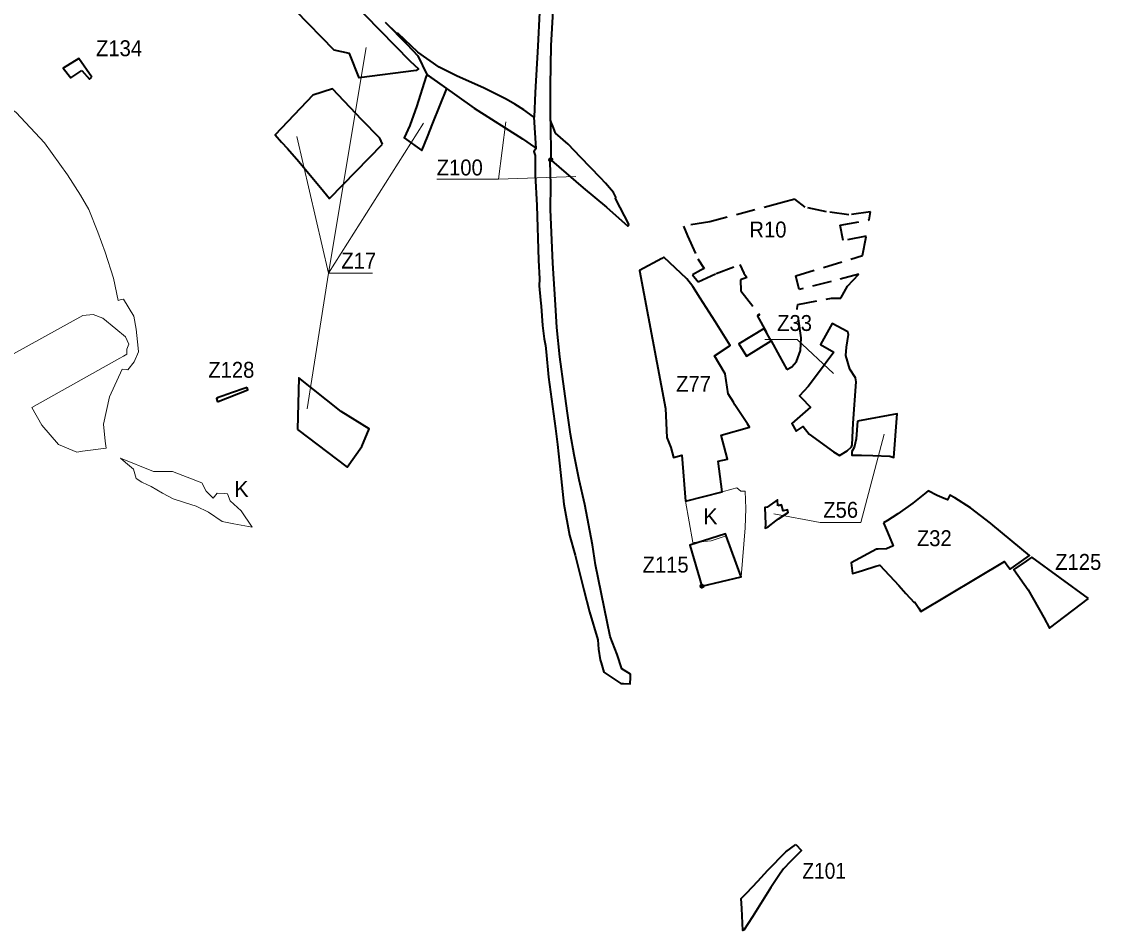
# Model space of a CAD drawing. Extents: x -650276 to -642489, y -1074311 to -1066658.
# Drawn here: x -646145 to -644519, y -1073665 to -1072295 of the extents above; entities that cross this region are included whole.
import ezdxf

# ---------------------------------------------------------------- set-up
doc = ezdxf.new("R2010")
doc.units = 0
doc.header["$LTSCALE"] = 9.6
doc.header["$PDMODE"] = 32
doc.header["$PDSIZE"] = 4.8
doc.linetypes.add('MEDIUM_DASHED', pattern=[4.5, 3, -1.5])
for name, color, linetype, lineweight in [('2', 7, 'Continuous', 40), ('3', 7, 'Continuous', 40), ('4', 7, 'Continuous', 40), ('42', 7, 'Continuous', 25), ('44', 7, 'Continuous', 40), ('45', 7, 'Continuous', 40), ('46', 7, 'Continuous', 13), ('47', 7, 'Continuous', 13), ('48', 7, 'Continuous', 35), ('59', 7, 'Continuous', 13), ('61', 7, 'MEDIUM_DASHED', 40), ('62', 7, 'Continuous', 35)]:
    doc.layers.add(name, color=color, linetype=linetype, lineweight=lineweight)

msp = doc.modelspace()

# ---------------------------------------------------------------- linework, layer by layer
at = {"layer": '2'}
for points in [[(-645834.208, -1072856.314), (-645837.027, -1072857.313), (-645839.908, -1072858.343), (-645842.74, -1072859.344), (-645845.619, -1072860.364), (-645848.628, -1072861.433), (-645851.48, -1072862.586), (-645850.187, -1072866.251), (-645850.17, -1072866.3), (-645849.705, -1072867.618), (-645849.703, -1072867.622)], [(-645849.703, -1072867.622), (-645848.52, -1072867.16), (-645803.84, -1072849.72), (-645805.159, -1072845.994)], [(-645805.159, -1072845.994), (-645808.177, -1072847.063), (-645811.148, -1072848.124), (-645813.978, -1072849.124), (-645816.948, -1072850.184), (-645819.779, -1072851.184), (-645822.726, -1072852.233), (-645825.527, -1072853.233), (-645828.409, -1072854.254), (-645834.208, -1072856.314)], [(-644536.62, -1073164.33), (-644622.03, -1073101.88), (-644630.58, -1073107.78), (-644648.95, -1073120.47), (-644627.53, -1073151.26)], [(-644627.53, -1073151.26), (-644604.13, -1073193), (-644595.18, -1073208.98), (-644536.62, -1073164.33)]]:
    msp.add_lwpolyline(points, dxfattribs=at)
at = {"layer": '3'}
for points in [[(-645503.98, -1072395.64), (-645532.75, -1072375.41), (-645535.05, -1072376.72), (-645549.6, -1072423.39), (-645551.54, -1072428.66), (-645559.92, -1072451.41), (-645568.38, -1072469.68), (-645541.56, -1072488.74), (-645541.09, -1072487.98), (-645533.15, -1072468.21), (-645524.87, -1072447.61)], [(-645600.945, -1072479.473), (-645605.17, -1072470.52), (-645632.1, -1072442.93), (-645632.1, -1072442.93), (-645676.53, -1072396.16), (-645706.039, -1072405.769), (-645763.06, -1072465.26), (-645753.128, -1072476.383), (-645744.38, -1072486.18), (-645726.95, -1072505.7), (-645709.92, -1072526.3), (-645694.51, -1072544.93), (-645680.87, -1072561.42)]]:
    msp.add_lwpolyline(points, close=True, dxfattribs=at)
at = {"layer": '4'}
for points in [[(-646039.16, -1072378.43), (-646058.64, -1072350.29), (-646082.55, -1072364.84), (-646071, -1072379.27), (-646054.43, -1072368.34)], [(-646054.43, -1072368.34), (-646042.65, -1072381.23), (-646039.16, -1072378.43)]]:
    msp.add_lwpolyline(points, dxfattribs=at)
at = {"layer": '42'}
msp.add_lwpolyline([(-644845.72, -1073050.14), (-644839.57, -1073064.5), (-644830.81, -1073084.98), (-644840.89, -1073089.3), (-644853.8, -1073089.99), (-644856.4, -1073090.13), (-644894.15, -1073110.3), (-644892.14, -1073126.36), (-644877.32, -1073121.83), (-644856.97, -1073115.6), (-644851, -1073113.77), (-644822.62, -1073144.71), (-644811.96, -1073156.75), (-644799.26, -1073170.13), (-644798.38, -1073169.56), (-644792.59, -1073178.73), (-644789.31, -1073183.93), (-644663.17, -1073108.27), (-644656.56, -1073117.4), (-644654.61, -1073120.1), (-644649.7, -1073116.65), (-644625.26, -1073099.51), (-644680.69, -1073053.67), (-644684.09, -1073050.8), (-644714.42, -1073027.62), (-644714.42, -1073027.62), (-644737.88, -1073012.62), (-644745.73, -1073008.64), (-644748.95, -1073015.64), (-644757.73, -1073012.05), (-644764.69, -1073008.87), (-644778.38, -1073001.84), (-644781.52, -1073004.39), (-644793.743, -1073014.293), (-644801.54, -1073020.61), (-644824.08, -1073036.56), (-644832.7, -1073042.34), (-644839.47, -1073046.89)], close=True, dxfattribs=at)
at = {"layer": '44'}
for points in [[(-645347.551, -1072443.527), (-645347.677, -1072391.355), (-645346.62, -1072330.914), (-645343.458, -1072278.998), (-645339.908, -1072235.158), (-645335.367, -1072185.207), (-645325.498, -1072102.789), (-645309.01, -1071998.147), (-645285.617, -1071875.733), (-645244.798, -1071696.585), (-645235.793, -1071663.703), (-645230.436, -1071634.261), (-645227.905, -1071625.277), (-645222.48, -1071606.08)], [(-645313.153, -1071883.081), (-645326.343, -1071952.807), (-645334.118, -1072001.954), (-645339.455, -1072031.565), (-645344.819, -1072081.225), (-645351.358, -1072130.815), (-645361.317, -1072232.824), (-645364.435, -1072280.268), (-645366.951, -1072331.609), (-645370.624, -1072401.447), (-645372.228, -1072438.764)], [(-645369.364, -1072485.931), (-645372.228, -1072438.764), (-645373.099, -1072438.135), (-645387.894, -1072427.453), (-645401.441, -1072419.033), (-645414.631, -1072411.611), (-645448.831, -1072394.325), (-645488.64, -1072376.782), (-645515.437, -1072363.447), (-645547.593, -1072340.827), (-645577.33, -1072312.704), (-645579.217, -1072312.425), (-645596.405, -1072296.114)], [(-645596.405, -1072296.114), (-645564.4, -1072328.61), (-645547.72, -1072346.19), (-645534.301, -1072374.332), (-645462.646, -1072425.015)], [(-645462.646, -1072425.015), (-645389.731, -1072471.612), (-645372.013, -1072484.069), (-645369.364, -1072485.931)], [(-645339.904, -1072462.677), (-645342.953, -1072455.042), (-645347.551, -1072443.527), (-645347.292, -1072502.877)], [(-645228.96, -1072600.865), (-645249.9, -1072561.25), (-645248.967, -1072559.511), (-645252.768, -1072552.178), (-645265.009, -1072538.358), (-645272.276, -1072530.154), (-645302.303, -1072499.014), (-645320.805, -1072479.495), (-645339.904, -1072462.677)], [(-645369.364, -1072485.931), (-645372.72, -1072490.314), (-645370.928, -1072496.619), (-645370.755, -1072525.734), (-645368.173, -1072571.881), (-645366.022, -1072654.462), (-645364.524, -1072682.575), (-645364.786, -1072692.977), (-645362.708, -1072714.781)], [(-645338.023, -1072755.969), (-645339.96, -1072721.587), (-645344.152, -1072658.857), (-645347.795, -1072577.893), (-645347.214, -1072540.97), (-645348.253, -1072505.583), (-645347.292, -1072502.877)], [(-645347.292, -1072502.877), (-645346.093, -1072503.921), (-645298.498, -1072545.352)], [(-645298.498, -1072545.352), (-645263.217, -1072574.314), (-645230.845, -1072602.888), (-645228.96, -1072600.865)], [(-645362.708, -1072714.781), (-645361.874, -1072723.527), (-645359.76, -1072752.865), (-645357.272, -1072772.771), (-645355.121, -1072782.993)], [(-645317.65, -1072916.642), (-645322.284, -1072885.085), (-645327.091, -1072848.387), (-645333.718, -1072799.987), (-645338.023, -1072755.969)], [(-645355.121, -1072782.993), (-645354.019, -1072792.454), (-645350.822, -1072830.388), (-645340.345, -1072908.029), (-645337.34, -1072932.073), (-645332.517, -1072974.538), (-645327.554, -1073022.214), (-645319.052, -1073068.6), (-645310.558, -1073098.946), (-645297.395, -1073151.294), (-645288.647, -1073184.518), (-645276.125, -1073226.571), (-645275.269, -1073240.71), (-645272.747, -1073256.762), (-645271.518, -1073261.16)], [(-645304.24, -1072985.372), (-645311.772, -1072947.945), (-645317.65, -1072916.642)], [(-645257.842, -1073221.36), (-645262.388, -1073199.409), (-645279.878, -1073113.356), (-645284.269, -1073083.286), (-645295.788, -1073022.556), (-645304.24, -1072985.372)], [(-645237.524, -1073292.361), (-645227.744, -1073292.735), (-645227.199, -1073283.366), (-645226.847, -1073278.345), (-645239.9, -1073270.025), (-645247.051, -1073248.736), (-645257.842, -1073221.36)], [(-645271.518, -1073261.16), (-645267.525, -1073275.443), (-645241.72, -1073292.2), (-645237.524, -1073292.361)]]:
    msp.add_lwpolyline(points, dxfattribs=at)
at = {"layer": '44', "lineweight": 13}
msp.add_lwpolyline([(-645519.31, -1072532.095), (-645425.882, -1072532.095), (-645415.202, -1072445.813), (-645425.882, -1072532.095), (-645309.26, -1072527.964)], dxfattribs=at)
msp.add_lwpolyline([(-645519.31, -1072532.095), (-645425.882, -1072532.095), (-645415.202, -1072445.813), (-645425.882, -1072532.095), (-645309.26, -1072527.964)], dxfattribs=at)
at = {"layer": '44'}
msp.add_lwpolyline([(-644977.924, -1073535.072), (-644969.117, -1073544.254), (-644985.66, -1073560.69), (-644996.41, -1073571.97), (-645001.267, -1073578.582), (-645015.55, -1073599.96), (-645043.35, -1073644.04), (-645056.06, -1073664.2), (-645057.87, -1073664.55), (-645059.35, -1073631.3), (-645060.009, -1073616.53), (-645051.513, -1073608.124), (-645035.303, -1073590.199), (-645020.11, -1073573.585), (-644993.044, -1073546.324)], close=True, dxfattribs=at)
msp.add_point((-645347.292, -1072502.877), dxfattribs=at)
at = {"layer": '45'}
for points in [[(-645817.219, -1072189.975), (-645768.649, -1072139.283), (-645740.45, -1072168.23), (-645559.34, -1072354.42), (-645546.82, -1072365.72), (-645550.41, -1072368.47), (-645636.37, -1072379.57), (-645650.78, -1072342.73), (-645674, -1072338), (-645789.298, -1072218.833)], [(-645144.37, -1073017.64), (-645088.62, -1073003.45), (-645095.04, -1072957.07), (-645080.61, -1072954.43), (-645083.13, -1072944.94), (-645090.34, -1072917.86), (-645047.42, -1072906.05), (-645050.6, -1072901.03), (-645069.55, -1072872.12), (-645071.87, -1072868.45), (-645079.81, -1072855.89), (-645084.47, -1072825.67), (-645100.27, -1072798.46), (-645076.66, -1072783.06), (-645099.58, -1072746.945), (-645121.96, -1072711.68), (-645133.26, -1072694.17), (-645142.1, -1072682.57), (-645176.757, -1072649.968), (-645180.05, -1072651.77), (-645213.34, -1072669.98), (-645174.13, -1072877.93), (-645172.28, -1072921.42), (-645166.48, -1072936.5), (-645162.379, -1072951.55), (-645149.84, -1072948.13)], [(-645025.61, -1072757.17), (-645063.6, -1072780.26), (-645051.94, -1072799.21), (-645015.02, -1072776.01)], [(-645025.61, -1072757.17), (-645063.6, -1072780.26), (-645051.94, -1072799.21), (-645015.02, -1072776.01)], [(-645729.36, -1072909.65), (-645654.16, -1072966.3), (-645632.23, -1072935.28), (-645620.92, -1072908.65), (-645663.52, -1072882.58), (-645726.9, -1072831.5)], [(-645729.36, -1072909.65), (-645654.16, -1072966.3), (-645632.23, -1072935.28), (-645620.92, -1072908.65), (-645663.52, -1072882.58), (-645726.9, -1072831.5)], [(-644884.94, -1072897.19), (-644886.98, -1072923.48), (-644889.65, -1072936.67), (-644893.37, -1072942.61), (-644893.59, -1072947.97), (-644878.86, -1072948.42), (-644861.93, -1072948.94), (-644835.99, -1072949.74), (-644830.25, -1072951.9), (-644825.25, -1072885.96)], [(-644884.94, -1072897.19), (-644886.98, -1072923.48), (-644889.65, -1072936.67), (-644893.37, -1072942.61), (-644893.59, -1072947.97), (-644878.86, -1072948.42), (-644861.93, -1072948.94), (-644835.99, -1072949.74), (-644830.25, -1072951.9), (-644825.25, -1072885.96)], [(-644845.72, -1073050.14), (-644839.57, -1073064.5), (-644830.81, -1073084.98), (-644840.89, -1073089.3), (-644853.8, -1073089.99), (-644856.4, -1073090.13), (-644894.15, -1073110.3), (-644892.14, -1073126.36), (-644877.32, -1073121.83), (-644856.97, -1073115.6), (-644851, -1073113.77), (-644822.62, -1073144.71), (-644811.96, -1073156.75), (-644799.26, -1073170.13), (-644798.38, -1073169.56), (-644792.59, -1073178.73), (-644789.31, -1073183.93), (-644663.17, -1073108.27), (-644656.56, -1073117.4), (-644654.61, -1073120.1), (-644649.7, -1073116.65), (-644625.26, -1073099.51), (-644680.69, -1073053.67), (-644684.09, -1073050.8), (-644714.42, -1073027.62), (-644714.42, -1073027.62), (-644737.88, -1073012.62), (-644745.73, -1073008.64), (-644748.95, -1073015.64), (-644757.73, -1073012.05), (-644764.69, -1073008.87), (-644778.38, -1073001.84), (-644781.52, -1073004.39), (-644793.743, -1073014.293), (-644801.54, -1073020.61), (-644824.08, -1073036.56), (-644832.7, -1073042.34), (-644839.47, -1073046.89)], [(-644845.72, -1073050.14), (-644839.57, -1073064.5), (-644830.81, -1073084.98), (-644840.89, -1073089.3), (-644853.8, -1073089.99), (-644856.4, -1073090.13), (-644894.15, -1073110.3), (-644892.14, -1073126.36), (-644877.32, -1073121.83), (-644856.97, -1073115.6), (-644851, -1073113.77), (-644822.62, -1073144.71), (-644811.96, -1073156.75), (-644799.26, -1073170.13), (-644798.38, -1073169.56), (-644792.59, -1073178.73), (-644789.31, -1073183.93), (-644663.17, -1073108.27), (-644656.56, -1073117.4), (-644654.61, -1073120.1), (-644649.7, -1073116.65), (-644625.26, -1073099.51), (-644680.69, -1073053.67), (-644684.09, -1073050.8), (-644714.42, -1073027.62), (-644714.42, -1073027.62), (-644737.88, -1073012.62), (-644745.73, -1073008.64), (-644748.95, -1073015.64), (-644757.73, -1073012.05), (-644764.69, -1073008.87), (-644778.38, -1073001.84), (-644781.52, -1073004.39), (-644793.743, -1073014.293), (-644801.54, -1073020.61), (-644824.08, -1073036.56), (-644832.7, -1073042.34), (-644839.47, -1073046.89)], [(-645004.82, -1073024.63), (-645005.31, -1073015.68), (-645021.1, -1073026.69), (-645024.71, -1073026.95), (-645023.6, -1073052.12), (-645023.88, -1073058.37), (-645019.57, -1073056.46), (-645007.99, -1073047.31), (-645003.78, -1073043.96), (-644989.34, -1073034.58), (-644990.25, -1073030.54), (-644997.09, -1073032.21), (-644999.23, -1073023.29)], [(-645004.82, -1073024.63), (-645005.31, -1073015.68), (-645021.1, -1073026.69), (-645024.71, -1073026.95), (-645023.6, -1073052.12), (-645023.88, -1073058.37), (-645019.57, -1073056.46), (-645007.99, -1073047.31), (-645003.78, -1073043.96), (-644989.34, -1073034.58), (-644990.25, -1073030.54), (-644997.09, -1073032.21), (-644999.23, -1073023.29)], [(-645119.34, -1073145.61), (-645060.1, -1073131.68), (-645082.6, -1073069.93), (-645083.681, -1073066.962), (-645137.5, -1073083.97)]]:
    msp.add_lwpolyline(points, close=True, dxfattribs=at)
for points in [[(-644902.18, -1072797.88), (-644901.35, -1072785.36), (-644898.29, -1072766.55), (-644899.2, -1072762.14), (-644922.88, -1072749.97), (-644940.8, -1072781.48), (-644920.46, -1072792.92)], [(-644902.18, -1072797.88), (-644901.35, -1072785.36), (-644898.29, -1072766.55), (-644899.2, -1072762.14), (-644922.88, -1072749.97), (-644940.8, -1072781.48), (-644920.46, -1072792.92)], [(-644920.46, -1072792.92), (-644945.2, -1072826.3), (-644959.24, -1072844.92), (-644972.28, -1072859.02), (-644969.93, -1072861.43), (-644955.49, -1072875.78), (-644983.93, -1072900.24), (-644977.16, -1072912.11), (-644966.57, -1072905.23), (-644957.79, -1072916.73), (-644921.18, -1072943.17), (-644911.87, -1072948.76), (-644900.2, -1072941.67), (-644893.77, -1072935.88), (-644892.86, -1072932.6), (-644891.2, -1072900.09), (-644886.61, -1072837.61), (-644887.99, -1072831.83), (-644896.45, -1072818.78), (-644902.18, -1072797.88)], [(-644920.46, -1072792.92), (-644945.2, -1072826.3), (-644959.24, -1072844.92), (-644972.28, -1072859.02), (-644969.93, -1072861.43), (-644955.49, -1072875.78), (-644983.93, -1072900.24), (-644977.16, -1072912.11), (-644966.57, -1072905.23), (-644957.79, -1072916.73), (-644921.18, -1072943.17), (-644911.87, -1072948.76), (-644900.2, -1072941.67), (-644893.77, -1072935.88), (-644892.86, -1072932.6), (-644891.2, -1072900.09), (-644886.61, -1072837.61), (-644887.99, -1072831.83), (-644896.45, -1072818.78), (-644902.18, -1072797.88)]]:
    msp.add_lwpolyline(points, dxfattribs=at)
msp.add_point((-645119.34, -1073145.61), dxfattribs=at)
at = {"layer": '46'}
for q in [(-645625.498, -1072333.934), (-645714.669, -1072878.528), (-645714.669, -1072878.528)]:
    msp.add_line((-645682.434, -1072673.943), q, dxfattribs=at)
for points in [[(-645024.402, -1072773.758), (-644975.968, -1072773.758), (-644921.076, -1072825.098)], [(-644844.691, -1072916.725), (-644879.683, -1073049.795), (-644940.921, -1073049.795), (-645010.906, -1073036.663)], [(-644844.691, -1072916.725), (-644879.683, -1073049.795), (-644940.921, -1073049.795), (-645010.906, -1073036.663)]]:
    msp.add_lwpolyline(points, dxfattribs=at)
at = {"layer": '47'}
for p, q in [((-645882.07, -1073025.22), (-645863.39, -1073034.25)), ((-645082.6, -1073069.93), (-645060.1, -1073131.68))]:
    msp.add_line(p, q, dxfattribs=at)
for points in [[(-645999.622, -1072714.927), (-646006.66, -1072681.4), (-646019.16, -1072642.35), (-646030.17, -1072612.31), (-646043.87, -1072578.12), (-646056.42, -1072556.49), (-646075.82, -1072525.54), (-646110.61, -1072477.49), (-646153.49, -1072431.54), (-646172.81, -1072418.2), (-646184.449, -1072410.256), (-646194.19, -1072404.62), (-646254.75, -1072404.25), (-646243.17, -1072432.88), (-646282.47, -1072474.34), (-646328.45, -1072504.81), (-646315.452, -1072531.573)], [(-645969.46, -1072787.03), (-645972.31, -1072758.48), (-645975.86, -1072738.61), (-645991.31, -1072712.86), (-645996.31, -1072714.11), (-645999.622, -1072714.927)], [(-646194.296, -1072760.193), (-646171.72, -1072803.51), (-646052.58, -1072737.82), (-646037.23, -1072736.38), (-646022.4, -1072741.58), (-646003.22, -1072757.85), (-645988.43, -1072769.93), (-645983.22, -1072780.88), (-645986.24, -1072788.33), (-645986.359, -1072796.127)], [(-645975.3, -1072807.37), (-645969.01, -1072792.28), (-645969.46, -1072787.03)], [(-645986.359, -1072796.127), (-645991.37, -1072798.84), (-645996.8, -1072801.88), (-646129.91, -1072876.24), (-646114.5, -1072902.8), (-646089.39, -1072931.92), (-646062.04, -1072943.58), (-646053.287, -1072942.399), (-646017.65, -1072937.59), (-646019.21, -1072926.91), (-646021.64, -1072901.6), (-646012.37, -1072860.3), (-645993.47, -1072818.44), (-645986.71, -1072819.26), (-645985.19, -1072819.72), (-645975.3, -1072807.37)], [(-645866.93, -1073002.72), (-645873.3, -1072989.79), (-645917.53, -1072972.93), (-645946.4, -1072973.05), (-645996.2, -1072952.69)], [(-645996.2, -1072952.69), (-645988.49, -1072959.28), (-645976.48, -1072969.55), (-645972.6, -1072983.41)], [(-645972.6, -1072983.41), (-645963.77, -1072989), (-645962.81, -1072989.45), (-645949.85, -1072995.57), (-645932.44, -1073005.5), (-645916.47, -1073014.03), (-645899.35, -1073019.65), (-645882.07, -1073025.22)], [(-645838.89, -1073006.18), (-645850.37, -1073005.42), (-645856.46, -1073013.07), (-645858.82, -1073010.74), (-645866.93, -1073002.72)], [(-645060.95, -1073002.68), (-645066.66, -1072997.3), (-645066.66, -1072997.3), (-645074.312, -1072999.359), (-645088.62, -1073003.45)], [(-645060.1, -1073131.68), (-645054.12, -1073057.62), (-645052.94, -1073028.58), (-645054.44, -1073002.54), (-645060.95, -1073002.68)], [(-645863.39, -1073034.25), (-645842.53, -1073048.19), (-645824.93, -1073051.83), (-645797.32, -1073056.62), (-645814.27, -1073032.11), (-645830.6, -1073016.92)], [(-645830.6, -1073016.92), (-645834.9, -1073006.45), (-645838.89, -1073006.18)], [(-645088.62, -1073003.45), (-645144.37, -1073017.64), (-645133.18, -1073079.73), (-645105.39, -1073077.58), (-645082.6, -1073069.93)]]:
    msp.add_lwpolyline(points, dxfattribs=at)
at = {"layer": '59'}
for p, q in [((-645682.434, -1072673.943), (-645539.175, -1072448)), ((-645682.434, -1072673.943), (-645729.938, -1072467.657)), ((-645616.267, -1072673.943), (-645682.434, -1072673.943))]:
    msp.add_line(p, q, dxfattribs=at)
at = {"layer": '61'}
msp.add_lwpolyline([(-645107.58, -1072596.47), (-645147.13, -1072602.79), (-645140.96, -1072617.82), (-645125.58, -1072652.42), (-645116.1, -1072667.08), (-645121.26, -1072669.32), (-645133.59, -1072676.49), (-645124.933, -1072686.721), (-645098.016, -1072674.425), (-645062.131, -1072660.856), (-645056.08, -1072674.07), (-645051.87, -1072680.22), (-645061.13, -1072683.98), (-645060.48, -1072700.69), (-645032.11, -1072737.28), (-645036.08, -1072737.88), (-645002.34, -1072799.06), (-644991.3, -1072819.12), (-644984.02, -1072814.87), (-644977, -1072807.06), (-644970.87, -1072790.69), (-644969.63, -1072771.21), (-644975.852, -1072727.059), (-644974.61, -1072720.9), (-644924.08, -1072711.8), (-644909.76, -1072711.64), (-644899.86, -1072693.27), (-644882.85, -1072675.56), (-644972.68, -1072698.65), (-644977.57, -1072677.66), (-644877.32, -1072647.4), (-644871.55, -1072618.07), (-644906.56, -1072624.79), (-644911.21, -1072601.67), (-644867.36, -1072593.58), (-644865.31, -1072581.58), (-644897.87, -1072585.78), (-644931.48, -1072581.26), (-644963.97, -1072574.57), (-644979.55, -1072562.44), (-644997.92, -1072567.23)], close=True, dxfattribs=at)

# ---------------------------------------------------------------- texts
at = {"layer": '44'}
for s, width, p in [('Z100', 0.95, (-645519.262, -1072526.583)), ('Z100', 0.95, (-645519.262, -1072526.583)), ('Z101', 0.9, (-644967.996, -1073586.746)), ('Z101', 0.9, (-644967.996, -1073586.746))]:
    msp.add_text(s, height=24, dxfattribs=dict(at, width=width)).set_placement(p)
at = {"layer": '46', "width": 0.95}
for s, p in [('Z33', (-645005.989, -1072761.006)), ('Z128', (-645863.685, -1072831.559)), ('Z77', (-645158.28, -1072852.64)), ('Z56', (-644936.499, -1073042.592)), ('Z56', (-644936.499, -1073042.592)), ('Z32', (-644795.309, -1073085.354)), ('Z32', (-644795.309, -1073085.354)), ('Z125', (-644586.786, -1073121.127)), ('Z115', (-645208.897, -1073125.218))]:
    msp.add_text(s, height=24, dxfattribs=at).set_placement(p)
at = {"layer": '48'}
for p in [(-645824.362, -1073011.011), (-645824.362, -1073011.011), (-645117.21, -1073052.527)]:
    msp.add_text('K', height=24, dxfattribs=at).set_placement(p)
at = {"layer": '59', "width": 0.95}
for s, p in [('Z134', (-646032.947, -1072346.856)), ('Z17', (-645663.172, -1072666.966))]:
    msp.add_text(s, height=24, dxfattribs=at).set_placement(p)
at = {"layer": '62', "width": 0.95}
msp.add_text('R10', height=24, dxfattribs=at).set_placement((-645047.84, -1072620.116))
msp.add_text('R10', height=24, dxfattribs=at).set_placement((-645047.84, -1072620.116))

doc.saveas('drawing.dxf')
